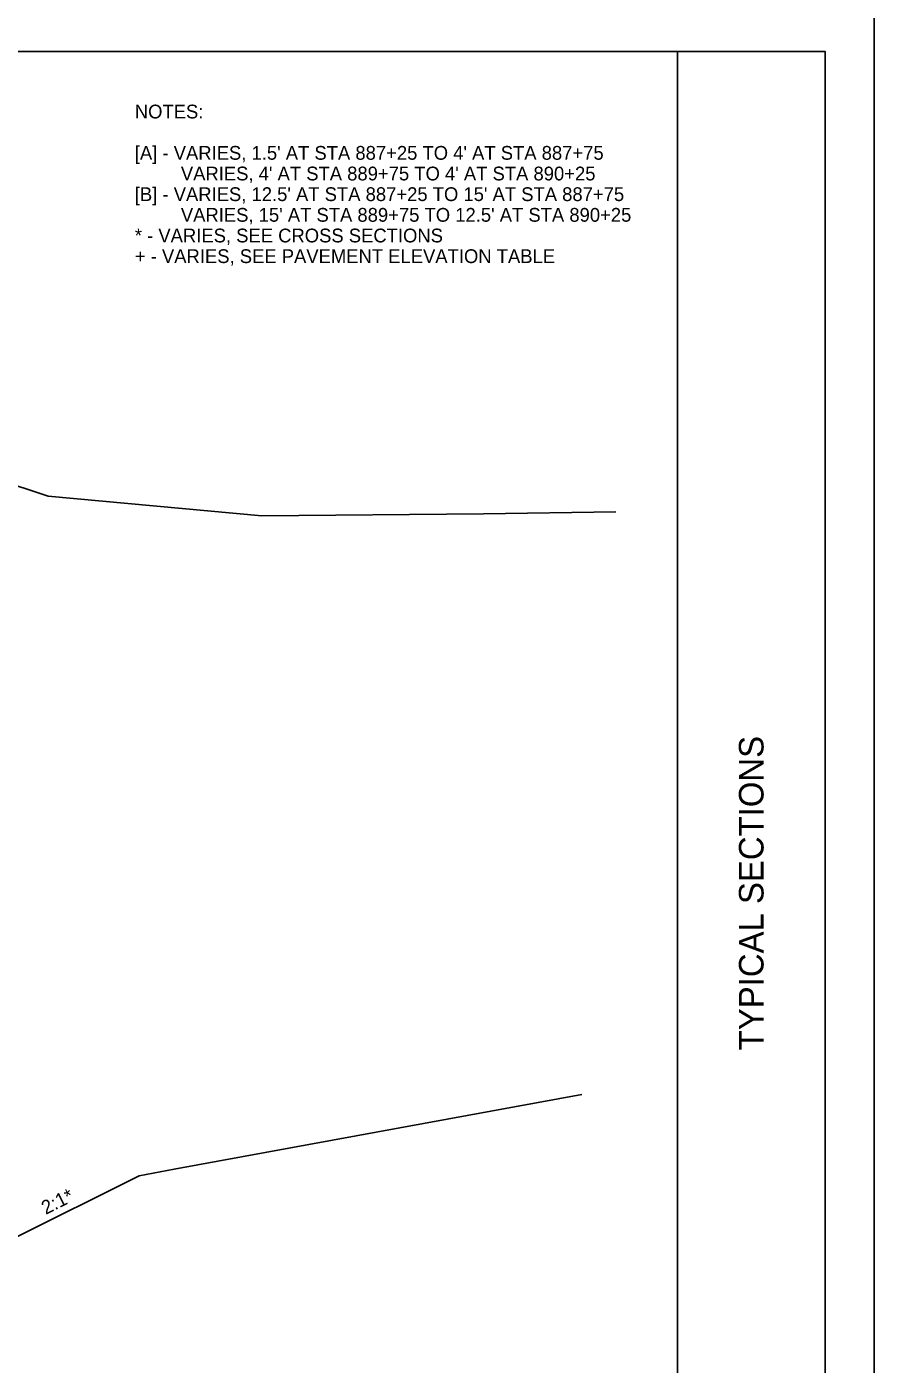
# Model space of a CAD drawing. Extents: x -345 to 102, y -108 to 100.
# Drawn here: x 76.16 to 102, y -41.54 to -0.75 of the extents above; entities that cross this region are included whole.
import ezdxf

# ---------------------------------------------------------------- set-up
doc = ezdxf.new("R2010")
doc.units = 0
for name, color, linetype in [('DT_X_Terrain_Ground_Line', 7, 'Continuous'), ('SH_Border', 7, 'Continuous'), ('SH_Cut_Line', 7, 'Continuous'), ('SH_Data', 7, 'Continuous'), ('TX_P_1', 7, 'Continuous'), ('TX_X_1', 7, 'Continuous'), ('XS_P_Finished_Grade', 7, 'Continuous')]:
    doc.layers.add(name, color=color, linetype=linetype)

msp = doc.modelspace()

# ---------------------------------------------------------------- linework, layer by layer
at = {"layer": 'DT_X_Terrain_Ground_Line'}
for points in [[(76.813, -15.067), (83.335, -15.664), (90.092, -15.602), (94.125, -15.539)], [(79.589, -35.787), (80.662, -35.589), (93.088, -33.311)]]:
    msp.add_lwpolyline(points, dxfattribs=at)
at = {"layer": 'SH_Border'}
msp.add_line((96, -64.5), (96, -1.5), dxfattribs=at)
msp.add_lwpolyline([(4.5, -1.5), (100.5, -1.5), (100.5, -64.5), (4.5, -64.5)], close=True, dxfattribs=at)
at = {"layer": 'SH_Cut_Line'}
msp.add_lwpolyline([(0, -66), (102, -66), (102, 0), (0, 0)], close=True, dxfattribs=at)
at = {"layer": 'XS_P_Finished_Grade'}
for p, q in [((70.082, -12.824), (76.813, -15.067)), ((79.589, -35.787), (75.717, -37.722))]:
    msp.add_line(p, q, dxfattribs=at)

# ---------------------------------------------------------------- texts
at = {"layer": 'SH_Data'}
msp.add_text('TYPICAL SECTIONS', height=0.75, rotation=90, dxfattribs=at).set_placement((98.625, -31.961))
at = {"layer": 'TX_P_1'}
msp.add_text('2:1*', height=0.42, rotation=26.5651, dxfattribs=at).set_placement((76.742, -36.982))
at = {"layer": 'TX_X_1'}
for s, p in [('NOTES:', (79.458, -3.546)), ("[A] - VARIES, 1.5' AT STA 887+25 TO 4' AT STA 887+75", (79.458, -4.806)), ("         VARIES, 4' AT STA 889+75 TO 4' AT STA 890+25", (79.458, -5.436)), ("[B] - VARIES, 12.5' AT STA 887+25 TO 15' AT STA 887+75", (79.458, -6.066)), ("         VARIES, 15' AT STA 889+75 TO 12.5' AT STA 890+25", (79.458, -6.696)), ('* - VARIES, SEE CROSS SECTIONS', (79.458, -7.326)), ('+ - VARIES, SEE PAVEMENT ELEVATION TABLE', (79.458, -7.956))]:
    msp.add_text(s, height=0.42, dxfattribs=at).set_placement(p)

doc.saveas('drawing.dxf')
